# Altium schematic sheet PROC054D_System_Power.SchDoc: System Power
size 558 x 431 mm; Date: Not shown in title block; ApprovedBy: Not shown in title block; CheckedBy: Not shown in title block; Author: Not shown in title block; CompanyName: Not shown in title block; DrawnBy: a0271760; Engineer: Not shown in title block; Organization: Not shown in title block; Address1: Not shown in title block; Address2: Not shown in title block; Address3: Not shown in title block; Address4: Not shown in title block; DocumentNumber: 3; Revision: Use project pAWRameter SCH_Rev; SheetNumber: 3; SheetTotal: 19; PageSetup: Record=PageOptions¦CenterHorizontal=True¦CenterVertical=True¦PrintScale=1.00¦XCorrection=1.00¦YCorrection=1.00¦PrintKind=0¦BorderSize=5000000¦LeftOffset=0¦BottomOffset=0¦Orientation=2¦PaperLength=1000¦PaperWidth=1000¦Scale=100¦PaperSource=15¦PrintQuality=600¦MediaType=1¦DitherType=10¦PaperKind=Letter¦PrintScaleMode=1
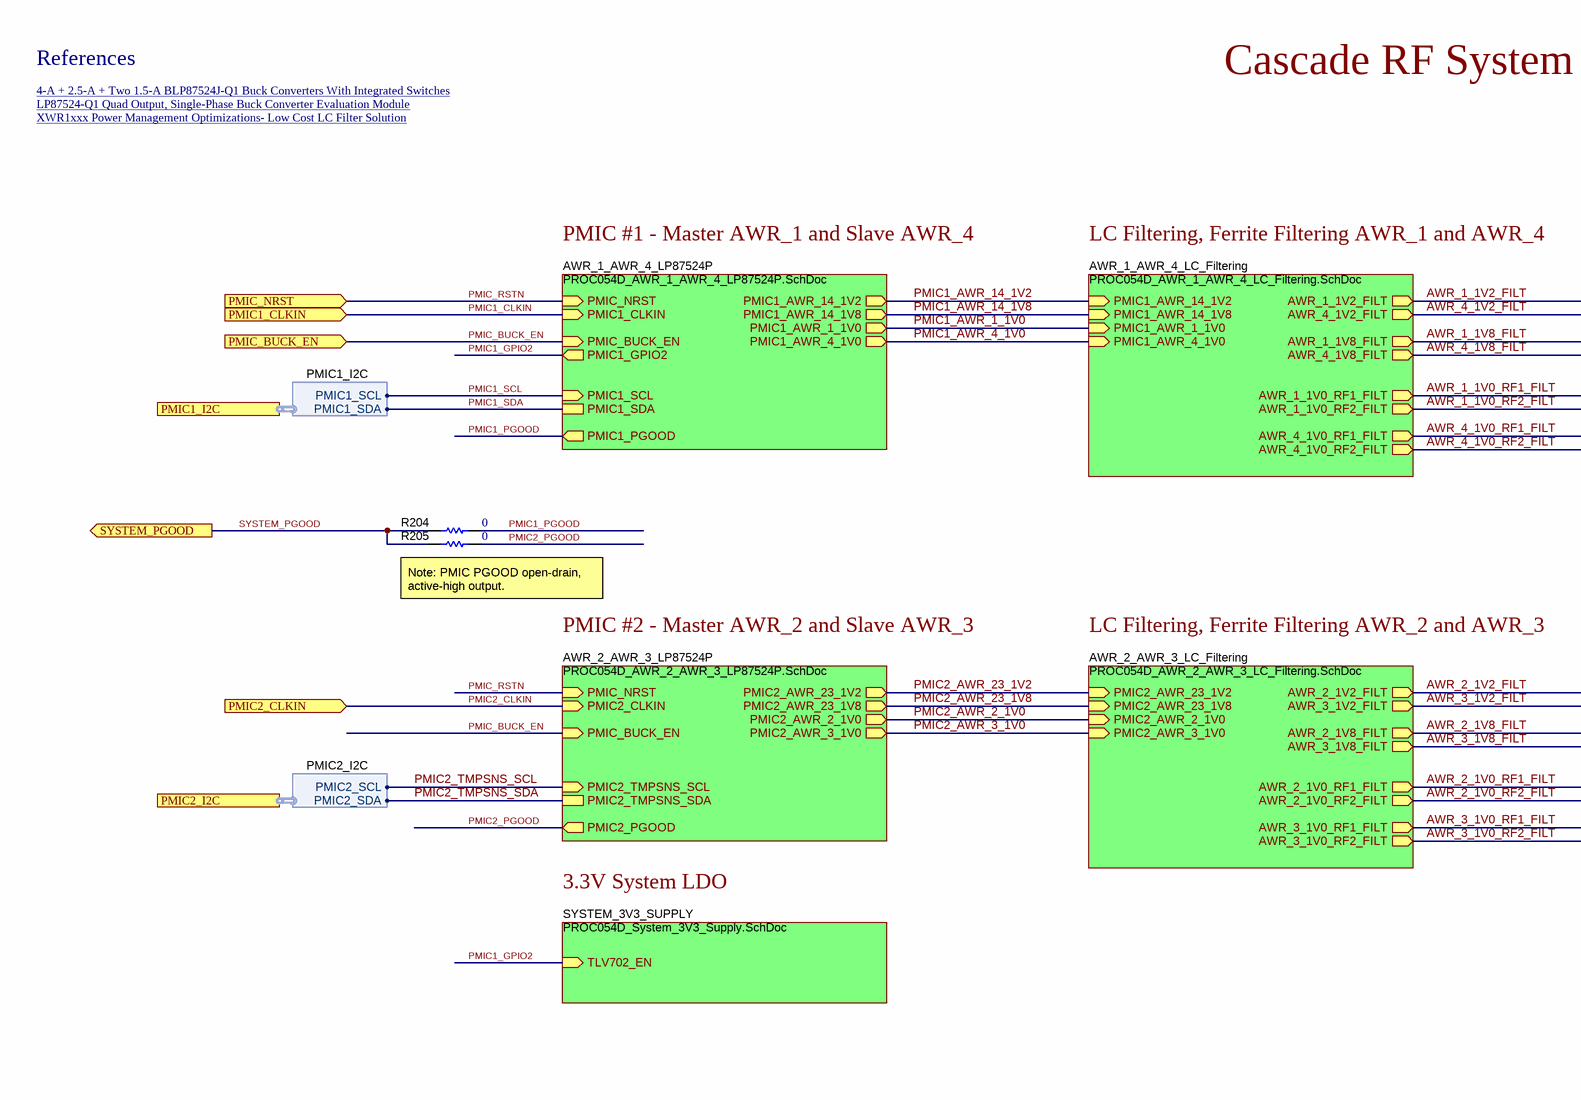
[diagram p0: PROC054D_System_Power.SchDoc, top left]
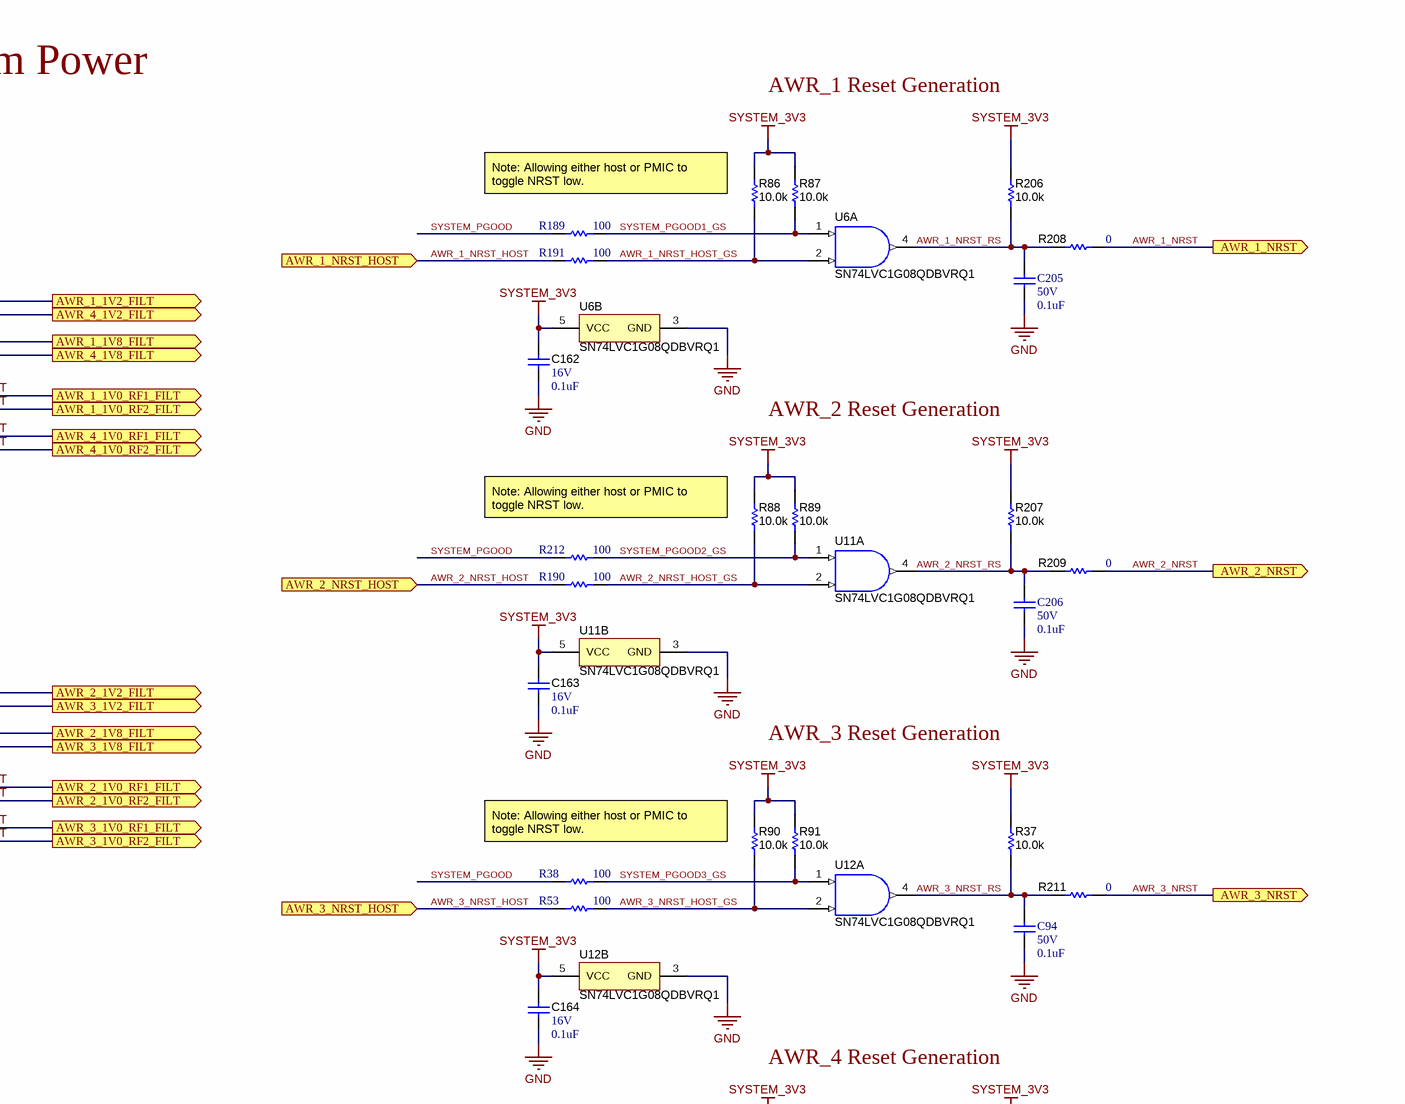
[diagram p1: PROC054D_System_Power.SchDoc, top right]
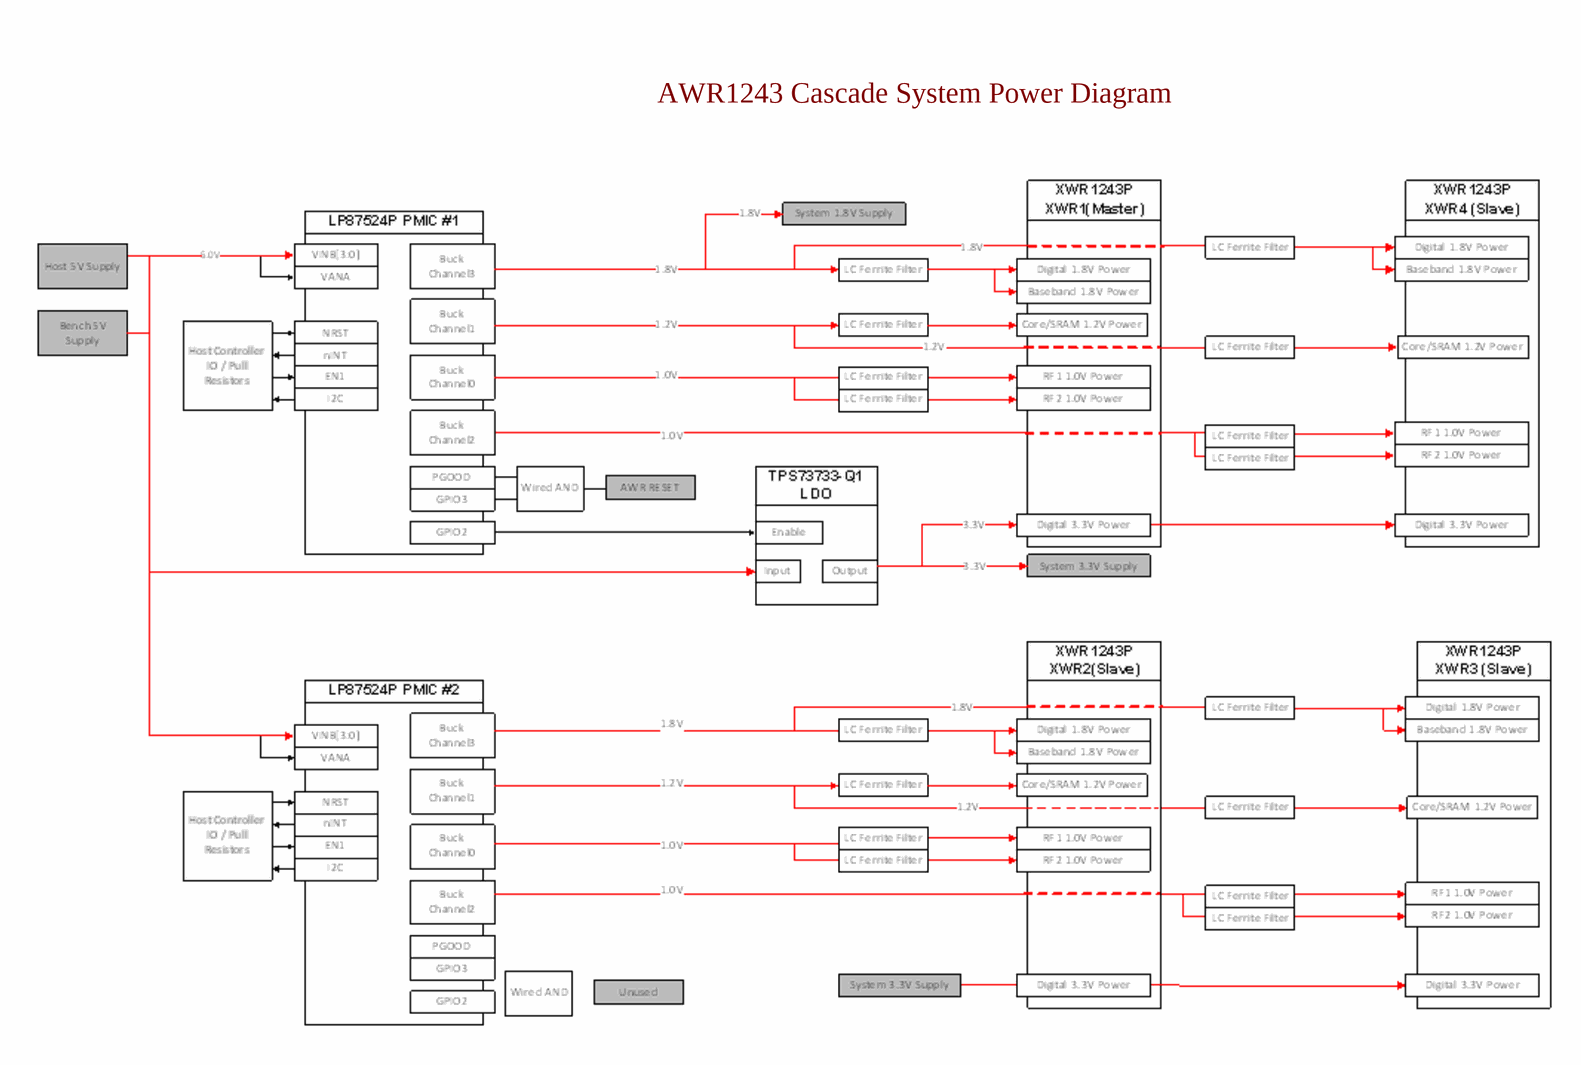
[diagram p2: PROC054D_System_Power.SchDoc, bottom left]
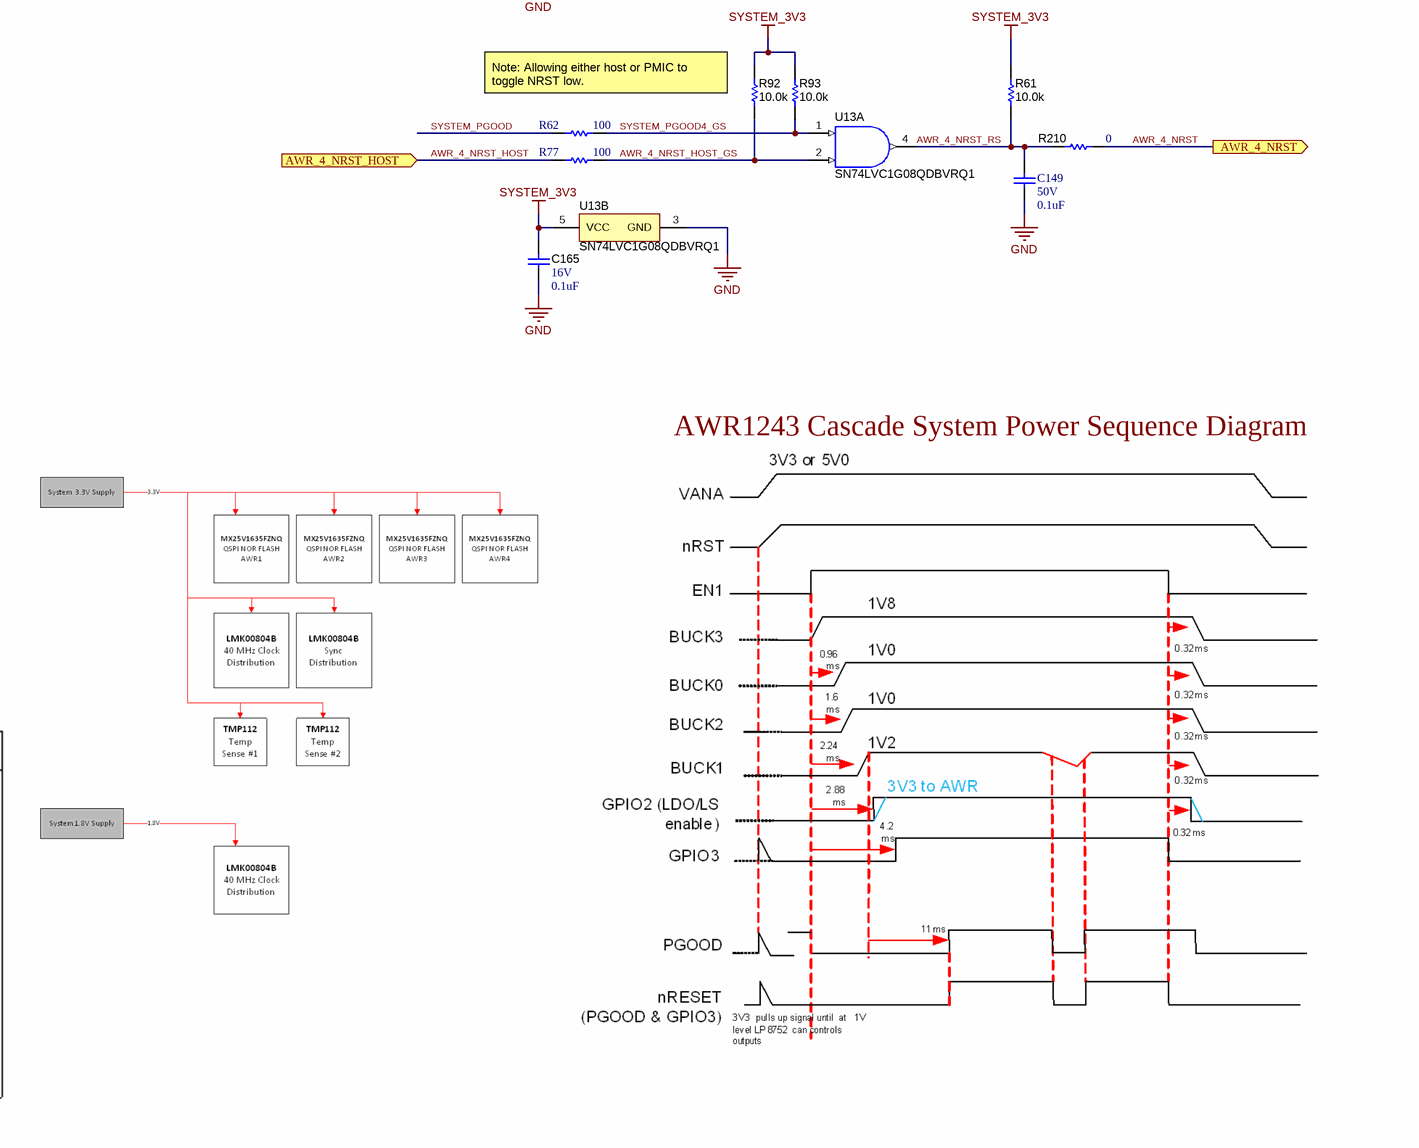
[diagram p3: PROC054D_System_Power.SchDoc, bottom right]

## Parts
C94  VDC_V: 50V  ValueDisplayed: 0.1uF  [0402]  (hidden comment: CGA2B3X7R1H104K050BB)
C149  VDC_V: 50V  ValueDisplayed: 0.1uF  [0402]  (hidden comment: CGA2B3X7R1H104K050BB)
C162  VDC_V: 16V  ValueDisplayed: 0.1uF  [0402]  (hidden comment: GCM155R71C104KA55D)
C163  VDC_V: 16V  ValueDisplayed: 0.1uF  [0402]  (hidden comment: GCM155R71C104KA55D)
C164  VDC_V: 16V  ValueDisplayed: 0.1uF  [0402]  (hidden comment: GCM155R71C104KA55D)
C165  VDC_V: 16V  ValueDisplayed: 0.1uF  [0402]  (hidden comment: GCM155R71C104KA55D)
C205  VDC_V: 50V  ValueDisplayed: 0.1uF  [0402]  (hidden comment: CGA2B3X7R1H104K050BB)
C206  VDC_V: 50V  ValueDisplayed: 0.1uF  [0402]  (hidden comment: CGA2B3X7R1H104K050BB)
R37  ValueDisplayed: 10.0k  [0402]  (hidden comment: CRCW040210K0FKED)
R38  ValueDisplayed: 100  [0402]  (hidden comment: MCS0402MD1000BE100)
R53  ValueDisplayed: 100  [0402]  (hidden comment: MCS0402MD1000BE100)
R61  ValueDisplayed: 10.0k  [0402]  (hidden comment: CRCW040210K0FKED)
R62  ValueDisplayed: 100  [0402]  (hidden comment: MCS0402MD1000BE100)
R77  ValueDisplayed: 100  [0402]  (hidden comment: MCS0402MD1000BE100)
R86  ValueDisplayed: 10.0k  [0402]  (hidden comment: CRCW040210K0FKED)
R87  ValueDisplayed: 10.0k  [0402]  (hidden comment: CRCW040210K0FKED)
R88  ValueDisplayed: 10.0k  [0402]  (hidden comment: CRCW040210K0FKED)
R89  ValueDisplayed: 10.0k  [0402]  (hidden comment: CRCW040210K0FKED)
R90  ValueDisplayed: 10.0k  [0402]  (hidden comment: CRCW040210K0FKED)
R91  ValueDisplayed: 10.0k  [0402]  (hidden comment: CRCW040210K0FKED)
R92  ValueDisplayed: 10.0k  [0402]  (hidden comment: CRCW040210K0FKED)
R93  ValueDisplayed: 10.0k  [0402]  (hidden comment: CRCW040210K0FKED)
R189  ValueDisplayed: 100  [0402]  (hidden comment: MCS0402MD1000BE100)
R190  ValueDisplayed: 100  [0402]  (hidden comment: MCS0402MD1000BE100)
R191  ValueDisplayed: 100  [0402]  (hidden comment: MCS0402MD1000BE100)
R204  ValueDisplayed: 0  [0402]  (hidden comment: ERJ-2GE0R00X)
R205  ValueDisplayed: 0  [0402]  (hidden comment: ERJ-2GE0R00X)
R206  ValueDisplayed: 10.0k  [0402]  (hidden comment: CRCW040210K0FKED)
R207  ValueDisplayed: 10.0k  [0402]  (hidden comment: CRCW040210K0FKED)
R208  ValueDisplayed: 0  [0402]  (hidden comment: ERJ-2GE0R00X)
R209  ValueDisplayed: 0  [0402]  (hidden comment: ERJ-2GE0R00X)
R210  ValueDisplayed: 0  [0402]  (hidden comment: ERJ-2GE0R00X)
R211  ValueDisplayed: 0  [0402]  (hidden comment: ERJ-2GE0R00X)
R212  ValueDisplayed: 100  [0402]  (hidden comment: MCS0402MD1000BE100)
U6  SN74LVC1G08QDBVRQ1  [DBV0005A_N]  (parts A,B of 2)
U11  SN74LVC1G08QDBVRQ1  [DBV0005A_N]  (parts A,B of 2)
U12  SN74LVC1G08QDBVRQ1  [DBV0005A_N]  (parts A,B of 2)
U13  SN74LVC1G08QDBVRQ1  [DBV0005A_N]  (parts A,B of 2)

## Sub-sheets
AWR_1_AWR_4_LC_Filtering = PROC054D_AWR_1_AWR_4_LC_Filtering.SchDoc: PMIC1_AWR_4_1V0 (in), PMIC1_AWR_1_1V0 (in), PMIC1_AWR_14_1V8 (in), PMIC1_AWR_14_1V2 (in), AWR_1_1V2_FILT (out), AWR_4_1V2_FILT (out), AWR_1_1V0_RF1_FILT (out), AWR_4_1V0_RF1_FILT (out), AWR_4_1V0_RF2_FILT (out), AWR_1_1V0_RF2_FILT (out), AWR_1_1V8_FILT (out), AWR_4_1V8_FILT (out)
AWR_1_AWR_4_LP87524P = PROC054D_AWR_1_AWR_4_LP87524P.SchDoc: PMIC_NRST (in), PMIC1_CLKIN (in), PMIC_BUCK_EN (in), PMIC1_SCL (in), PMIC1_SDA, PMIC1_PGOOD (out), PMIC1_GPIO2 (out), PMIC1_AWR_1_1V0 (out), PMIC1_AWR_14_1V8 (out), PMIC1_AWR_4_1V0 (out), PMIC1_AWR_14_1V2 (out)
AWR_2_AWR_3_LC_Filtering = PROC054D_AWR_2_AWR_3_LC_Filtering.SchDoc: AWR_2_1V2_FILT (out), PMIC2_AWR_3_1V0 (in), PMIC2_AWR_2_1V0 (in), PMIC2_AWR_23_1V8 (in), PMIC2_AWR_23_1V2 (in), AWR_3_1V2_FILT (out), AWR_3_1V0_RF1_FILT (out), AWR_3_1V0_RF2_FILT (out), AWR_2_1V0_RF1_FILT (out), AWR_2_1V0_RF2_FILT (out), AWR_2_1V8_FILT (out), AWR_3_1V8_FILT (out)
AWR_2_AWR_3_LP87524P = PROC054D_AWR_2_AWR_3_LP87524P.SchDoc: PMIC_NRST (in), PMIC2_CLKIN (in), PMIC_BUCK_EN (in), PMIC2_TMPSNS_SCL (in), PMIC2_TMPSNS_SDA, PMIC2_PGOOD (out), PMIC2_AWR_3_1V0 (out), PMIC2_AWR_23_1V8 (out), PMIC2_AWR_2_1V0 (out), PMIC2_AWR_23_1V2 (out)
SYSTEM_3V3_SUPPLY = PROC054D_System_3V3_Supply.SchDoc: TLV702_EN (in)

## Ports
AWR_1_1V0_RF1_FILT (out), AWR_1_1V0_RF2_FILT (out), AWR_1_1V2_FILT (out), AWR_1_1V8_FILT (out), AWR_1_NRST (out), AWR_1_NRST_HOST (in), AWR_2_1V0_RF1_FILT (out), AWR_2_1V0_RF2_FILT (out), AWR_2_1V2_FILT (out), AWR_2_1V8_FILT (out), AWR_2_NRST (out), AWR_2_NRST_HOST (in), AWR_3_1V0_RF1_FILT (out), AWR_3_1V0_RF2_FILT (out), AWR_3_1V2_FILT (out), AWR_3_1V8_FILT (out), AWR_3_NRST (out), AWR_3_NRST_HOST (in), AWR_4_1V0_RF1_FILT (out), AWR_4_1V0_RF2_FILT (out), AWR_4_1V2_FILT (out), AWR_4_1V8_FILT (out), AWR_4_NRST (out), AWR_4_NRST_HOST (in), PMIC1_CLKIN (in), PMIC1_I2C (harness PMIC1_I2C), PMIC2_CLKIN (in), PMIC2_I2C (harness PMIC2_I2C), PMIC_BUCK_EN (in), PMIC_NRST (in), SYSTEM_PGOOD (out)

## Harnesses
PMIC2_I2C: PMIC2_SCL, PMIC2_SDA
PMIC1_I2C: PMIC1_SCL, PMIC1_SDA

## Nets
GND: C94.2 C149.2 C162.2 C163.2 C164.2 C165.2 C205.2 C206.2 U6.3(GND) U11.3(GND) U12.3(GND) U13.3(GND)
SYSTEM_3V3: C162.1 C163.1 C164.1 C165.1 R37.2 R61.2 R86.2 R87.2 R88.2 R89.2 R90.2 R91.2 R92.2 R93.2 R206.2 R207.2 U6.5(VCC) U11.5(VCC) U12.5(VCC) U13.5(VCC)
AWR_1_1V0_RF1_FILT: port AWR_1_1V0_RF1_FILT, sheet AWR_1_AWR_4_LC_Filtering/AWR_1_1V0_RF1_FILT
AWR_1_1V0_RF2_FILT: port AWR_1_1V0_RF2_FILT, sheet AWR_1_AWR_4_LC_Filtering/AWR_1_1V0_RF2_FILT
AWR_1_1V2_FILT: port AWR_1_1V2_FILT, sheet AWR_1_AWR_4_LC_Filtering/AWR_1_1V2_FILT
AWR_1_1V8_FILT: port AWR_1_1V8_FILT, sheet AWR_1_AWR_4_LC_Filtering/AWR_1_1V8_FILT
AWR_1_NRST: R208.2 ; port AWR_1_NRST
AWR_1_NRST_HOST: R191.1 ; port AWR_1_NRST_HOST
AWR_1_NRST_HOST_GS: R86.1 R191.2 U6.2(B)
AWR_1_NRST_RS: C205.1 R206.1 R208.1 U6.4(Y)
AWR_2_1V0_RF1_FILT: port AWR_2_1V0_RF1_FILT, sheet AWR_2_AWR_3_LC_Filtering/AWR_2_1V0_RF1_FILT
AWR_2_1V0_RF2_FILT: port AWR_2_1V0_RF2_FILT, sheet AWR_2_AWR_3_LC_Filtering/AWR_2_1V0_RF2_FILT
AWR_2_1V2_FILT: port AWR_2_1V2_FILT, sheet AWR_2_AWR_3_LC_Filtering/AWR_2_1V2_FILT
AWR_2_1V8_FILT: port AWR_2_1V8_FILT, sheet AWR_2_AWR_3_LC_Filtering/AWR_2_1V8_FILT
AWR_2_NRST: R209.2 ; port AWR_2_NRST
AWR_2_NRST_HOST: R190.1 ; port AWR_2_NRST_HOST
AWR_2_NRST_HOST_GS: R88.1 R190.2 U11.2(B)
AWR_2_NRST_RS: C206.1 R207.1 R209.1 U11.4(Y)
AWR_3_1V0_RF1_FILT: port AWR_3_1V0_RF1_FILT, sheet AWR_2_AWR_3_LC_Filtering/AWR_3_1V0_RF1_FILT
AWR_3_1V0_RF2_FILT: port AWR_3_1V0_RF2_FILT, sheet AWR_2_AWR_3_LC_Filtering/AWR_3_1V0_RF2_FILT
AWR_3_1V2_FILT: port AWR_3_1V2_FILT, sheet AWR_2_AWR_3_LC_Filtering/AWR_3_1V2_FILT
AWR_3_1V8_FILT: port AWR_3_1V8_FILT, sheet AWR_2_AWR_3_LC_Filtering/AWR_3_1V8_FILT
AWR_3_NRST: R211.2 ; port AWR_3_NRST
AWR_3_NRST_HOST: R53.1 ; port AWR_3_NRST_HOST
AWR_3_NRST_HOST_GS: R53.2 R90.1 U12.2(B)
AWR_3_NRST_RS: C94.1 R37.1 R211.1 U12.4(Y)
AWR_4_1V0_RF1_FILT: port AWR_4_1V0_RF1_FILT, sheet AWR_1_AWR_4_LC_Filtering/AWR_4_1V0_RF1_FILT
AWR_4_1V0_RF2_FILT: port AWR_4_1V0_RF2_FILT, sheet AWR_1_AWR_4_LC_Filtering/AWR_4_1V0_RF2_FILT
AWR_4_1V2_FILT: port AWR_4_1V2_FILT, sheet AWR_1_AWR_4_LC_Filtering/AWR_4_1V2_FILT
AWR_4_1V8_FILT: port AWR_4_1V8_FILT, sheet AWR_1_AWR_4_LC_Filtering/AWR_4_1V8_FILT
AWR_4_NRST: R210.2 ; port AWR_4_NRST
AWR_4_NRST_HOST: R77.1 ; port AWR_4_NRST_HOST
AWR_4_NRST_HOST_GS: R77.2 R92.1 U13.2(B)
AWR_4_NRST_RS: C149.1 R61.1 R210.1 U13.4(Y)
PMIC1_AWR_1_1V0: sheet AWR_1_AWR_4_LP87524P/PMIC1_AWR_1_1V0, sheet AWR_1_AWR_4_LC_Filtering/PMIC1_AWR_1_1V0
PMIC1_AWR_4_1V0: sheet AWR_1_AWR_4_LP87524P/PMIC1_AWR_4_1V0, sheet AWR_1_AWR_4_LC_Filtering/PMIC1_AWR_4_1V0
PMIC1_AWR_14_1V2: sheet AWR_1_AWR_4_LP87524P/PMIC1_AWR_14_1V2, sheet AWR_1_AWR_4_LC_Filtering/PMIC1_AWR_14_1V2
PMIC1_AWR_14_1V8: sheet AWR_1_AWR_4_LP87524P/PMIC1_AWR_14_1V8, sheet AWR_1_AWR_4_LC_Filtering/PMIC1_AWR_14_1V8
PMIC1_CLKIN: port PMIC1_CLKIN, sheet AWR_1_AWR_4_LP87524P/PMIC1_CLKIN
PMIC1_GPIO2: sheet AWR_1_AWR_4_LP87524P/PMIC1_GPIO2, sheet SYSTEM_3V3_SUPPLY/TLV702_EN
PMIC1_PGOOD: R204.2 ; sheet AWR_1_AWR_4_LP87524P/PMIC1_PGOOD
PMIC1_SCL: sheet AWR_1_AWR_4_LP87524P/PMIC1_SCL, port PMIC1_I2C.PMIC1_SCL
PMIC1_SDA: sheet AWR_1_AWR_4_LP87524P/PMIC1_SDA, port PMIC1_I2C.PMIC1_SDA
PMIC2_AWR_2_1V0: sheet AWR_2_AWR_3_LP87524P/PMIC2_AWR_2_1V0, sheet AWR_2_AWR_3_LC_Filtering/PMIC2_AWR_2_1V0
PMIC2_AWR_3_1V0: sheet AWR_2_AWR_3_LP87524P/PMIC2_AWR_3_1V0, sheet AWR_2_AWR_3_LC_Filtering/PMIC2_AWR_3_1V0
PMIC2_AWR_23_1V2: sheet AWR_2_AWR_3_LP87524P/PMIC2_AWR_23_1V2, sheet AWR_2_AWR_3_LC_Filtering/PMIC2_AWR_23_1V2
PMIC2_AWR_23_1V8: sheet AWR_2_AWR_3_LP87524P/PMIC2_AWR_23_1V8, sheet AWR_2_AWR_3_LC_Filtering/PMIC2_AWR_23_1V8
PMIC2_CLKIN: port PMIC2_CLKIN, sheet AWR_2_AWR_3_LP87524P/PMIC2_CLKIN
PMIC2_PGOOD: R205.2 ; sheet AWR_2_AWR_3_LP87524P/PMIC2_PGOOD
PMIC2_TMPSNS_SCL: sheet AWR_2_AWR_3_LP87524P/PMIC2_TMPSNS_SCL, port PMIC2_I2C.PMIC2_SCL
PMIC2_TMPSNS_SDA: sheet AWR_2_AWR_3_LP87524P/PMIC2_TMPSNS_SDA, port PMIC2_I2C.PMIC2_SDA
PMIC_BUCK_EN: port PMIC_BUCK_EN, sheet AWR_1_AWR_4_LP87524P/PMIC_BUCK_EN, sheet AWR_2_AWR_3_LP87524P/PMIC_BUCK_EN
PMIC_RSTN: port PMIC_NRST, sheet AWR_1_AWR_4_LP87524P/PMIC_NRST, sheet AWR_2_AWR_3_LP87524P/PMIC_NRST
SYSTEM_PGOOD: R38.1 R62.1 R189.1 R204.1 R205.1 R212.1 ; port SYSTEM_PGOOD
SYSTEM_PGOOD1_GS: R87.1 R189.2 U6.1(A)
SYSTEM_PGOOD2_GS: R89.1 R212.2 U11.1(A)
SYSTEM_PGOOD3_GS: R38.2 R91.1 U12.1(A)
SYSTEM_PGOOD4_GS: R62.2 R93.1 U13.1(A)

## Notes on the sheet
- References
- Cascade RF System Power
- LP87524-Q1 Quad Output, Single-Phase Buck Converter Evaluation Module <http://www.ti.com/tool/lp87524q1evm>
- 4-A + 2.5-A + Two 1.5-A BLP87524J-Q1 Buck Converters With Integrated Switches <http://www.ti.com/product/lp87524j-q1>
- XWR1xxx Power Management Optimizations- Low Cost LC Filter Solution <http://www.ti.com/lit/pdf/swra577>
- AWR_1 Reset Generation
- Note: Allowing either host or PMIC to toggle NRST low.
- PMIC #1 - Master AWR_1 and Slave AWR_4
- LC Filtering, Ferrite Filtering AWR_1 and AWR_4
- AWR_2 Reset Generation
- (near R205) Note: PMIC PGOOD open-drain, active-high output.
- PMIC #2 - Master AWR_2 and Slave AWR_3
- LC Filtering, Ferrite Filtering AWR_2 and AWR_3
- AWR_3 Reset Generation
- 3.3V System LDO
- AWR_4 Reset Generation
- AWR1243 Cascade System Power Diagram
- AWR1243 Cascade System Power Sequence Diagram

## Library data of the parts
C94 C149 C205 C206 = CMP-0006325-2: CAP, CERM, 0.1 uF, 50 V, +/- 10%, X7R, AEC-Q200 Grade 1, 0402; Manufacturer: TDK; TaMin_C: -55°C; ESR_ohm: 0.039064; Polarized: N; SizeAreaWB_mm2: 3; Value1: 0.039064 ohm; U/M: EA; Value: 0.1uF; TaMax_C: 125°C; SizeZ_mm: 0.6; SizeX_mm: 1; SizeY_mm: 0.5; AEC Qualified: Y; Cap_F: 100nF; IRMS_A: 8.14669dA; AEC Category: Q200
C162-C165 = CMP-0006351-2: CAP, CERM, 0.1 uF, 16 V, +/- 10%, X7R, 0402; Manufacturer: MuRata; TaMin_C: -55°C; Polarized: N; SizeAreaWB_mm2: 3; Value1: Unknown; U/M: EA; Value: 0.1uF; TaMax_C: 125°C; SizeZ_mm: 0.6; SizeX_mm: 1; SizeY_mm: 0.5; Cap_F: 100nF; AEC Category: Q200
R37 R61 R86-R93 R206 R207 = CMP-0025958-3: RES, 10.0 k, 1%, 0.063 W, AEC-Q200 Grade 0, 0402; Manufacturer: Vishay-Dale; Power_W: 63mW; TempCo: 100 ppm/C; Value_Code: 10k0; Value: 10.0k; EIA_Code: E96; Res_ohm: 10k; SizeX_mm: 1; SizeY_mm: 0.5; SizeZ_mm: 0.6; Value2: 0.063W; AEC Qualified: Y; VDC_V: 50V; AEC Category: Q200; AEC Grade: 0
R38 R53 R62 R77 R189-R191 R212 = CMP-0026794-1: RES, 100, 0.1%, 0.1 W, AEC-Q200 Grade 0, 0402; Manufacturer: Vishay/Beyschlag; Power_W: 100mW; TempCo: 25 ppm/C; Value_Code: 100R; U/M: EA; Value: 100; EIA_Code: E192; SizeX_mm: 1; SizeY_mm: 0.5; SizeZ_mm: 0.6; Value2: 0.1W; AEC Qualified: Y; VDC_V: 50V; AEC Grade: 0; AEC Category: Q200
R204 R205 R208-R211 = CMP-0026992-3: RES, 0, 5%, 0.1 W, AEC-Q200 Grade 0, 0402; Manufacturer: Panasonic; Power_W: 100mW; TempCo: 600 ppm/C; Value_Code: 0000; Value: 0; EIA_Code: E24; SizeX_mm: 1; SizeY_mm: 0.5; SizeZ_mm: 0.6; Value2: 0.1W; AEC Qualified: Y; VDC_V: 50V; AEC Category: Q200; SizeAreaWB_mm2: 3
U6 U11-U13 = CMP-0051570-2: Automotive Catalog Single 2-Input Positive-AND Gate, DBV0005A, LARGE T&R; Manufacturer: Texas Instruments; Generic Part Number: SN74LVC1G08-Q1; VCC(Min)(V): 1.65; Gate Type: AND; 3-State Output: No; tpd @ Nom Voltage(Max)(ns): 8,5.5,4.5,4; Logic: True; Voltage(Nom)(V): 1.8,2.5,3.3,5; ICC @ Nom Voltage(Max)(mA): 0.01; Input Type: CMOS/TTL; Output Type: CMOS; Output Drive (IOL/IOH)(Max)(mA): 32/-32; Bits(#): 1; Technology Family: LVC; F @ Nom Voltage(Max)(Mhz): 150; VCC(Max)(V): 5.5; AEC Category: Q200; AEC Qualified: Y; CompType: IC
